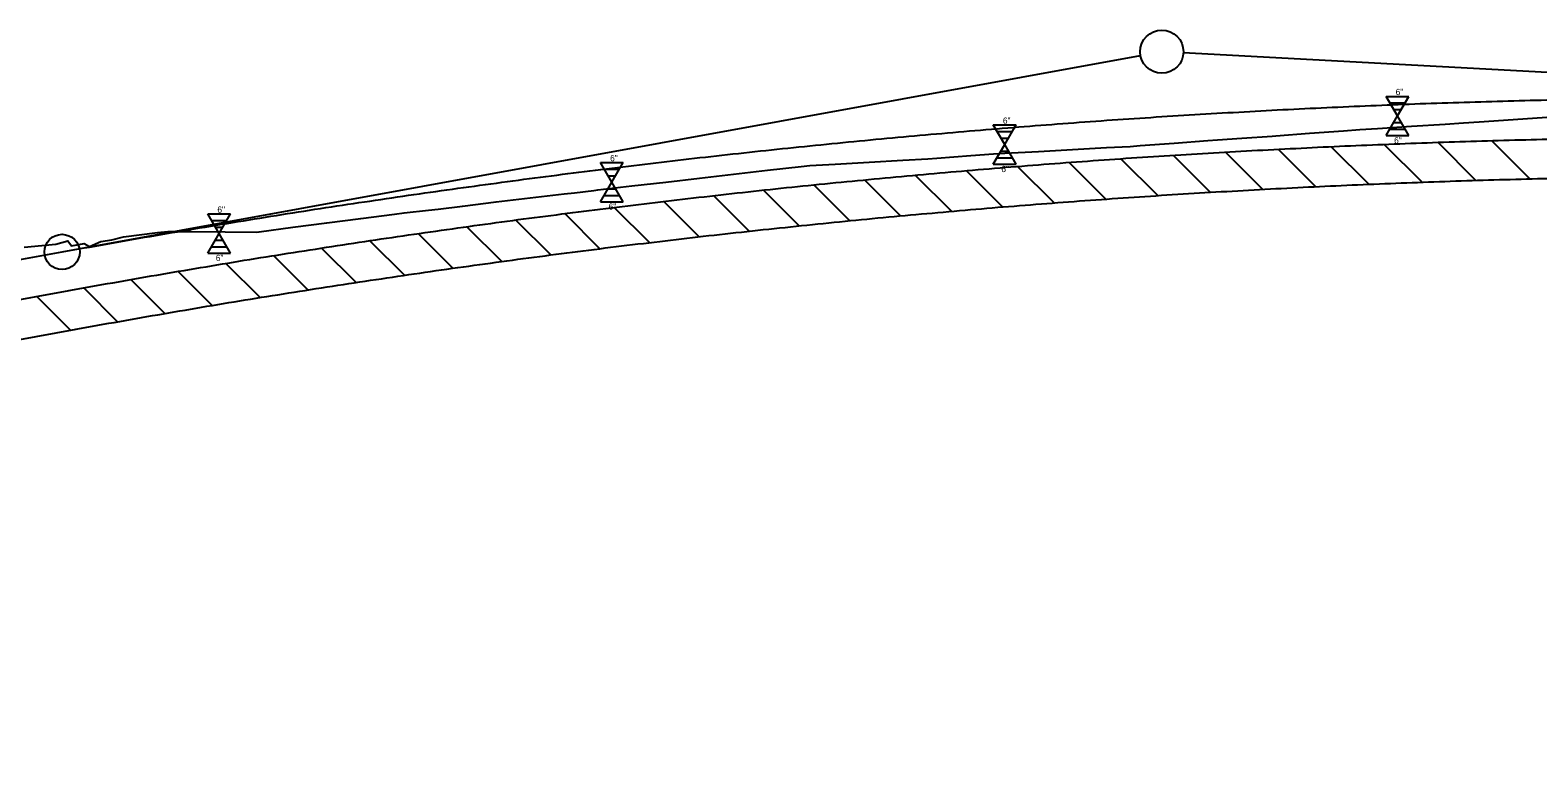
# Model space of a CAD drawing. Extents: x 579185 to 595036, y -53221 to -44640.
# Drawn here: x 584352.2 to 584544.1, y -46885.4 to -46791.5 of the extents above; entities that cross this region are included whole.
import ezdxf

# ---------------------------------------------------------------- set-up
doc = ezdxf.new("R2010")
doc.units = 0
for name, color, linetype in [('Exist Vertical Profile Ground Line', 7, 'Continuous'), ('Old_Level_2', 7, 'Continuous'), ('Prop Vertical Profile Curve Label', 7, 'Continuous'), ('Prop Vertical Profile Grade', 7, 'Continuous'), ('Prop VPI Label', 7, 'Continuous'), ('Scratch_Level_1', 7, 'Continuous')]:
    doc.layers.add(name, color=color, linetype=linetype)

msp = doc.modelspace()

# ---------------------------------------------------------------- linework, layer by layer
at = {"layer": 'Exist Vertical Profile Ground Line'}
msp.add_lwpolyline([(584351.4, -46819.17), (584355.43, -46818.8), (584356.96, -46818.38), (584357.45, -46819), (584359.06, -46818.72), (584359.75, -46819.09), (584361.16, -46818.46), (584362.57, -46818.25), (584364.06, -46817.85), (584368.38, -46817.32), (584369.71, -46817.16), (584372.69, -46817.18), (584377.01, -46817.21), (584381.02, -46817.24), (584381.32, -46817.2), (584385.64, -46816.64), (584389.95, -46816.07), (584394.26, -46815.51), (584398.58, -46814.95), (584399.79, -46814.79), (584402.89, -46814.46), (584404.13, -46814.33), (584407.21, -46813.93), (584411.52, -46813.39), (584415.84, -46812.89), (584420.15, -46812.38), (584421.47, -46812.23), (584423.92, -46811.94), (584424.46, -46811.87), (584428.78, -46811.37), (584433.09, -46810.87), (584437.41, -46810.37), (584441.72, -46809.87), (584446.04, -46809.38), (584450.35, -46808.89), (584451.42, -46808.77), (584454.66, -46808.59), (584458.98, -46808.34), (584463.29, -46808.1), (584466.46, -46807.93), (584467.61, -46807.84), (584471.92, -46807.51), (584474.8, -46807.29), (584476.24, -46807.21), (584480.55, -46806.97), (584484.86, -46806.73), (584489.18, -46806.49), (584492.21, -46806.33), (584493.49, -46806.23), (584497.81, -46805.9), (584502.12, -46805.58), (584503.32, -46805.49), (584506.44, -46805.28), (584510.27, -46805.02), (584510.75, -46804.98), (584515.06, -46804.66), (584519.38, -46804.35), (584521.46, -46804.19), (584523.69, -46804.05), (584528.01, -46803.77), (584532.32, -46803.5), (584534.65, -46803.35), (584536.64, -46803.21), (584540.95, -46802.9), (584545.26, -46802.6)], dxfattribs=at)
at = {"layer": 'Old_Level_2'}
for p, q in [((584526.24, -46802.46), (584524.79, -46799.96)), ((584524.79, -46799.96), (584527.68, -46799.96)), ((584526.24, -46802.46), (584527.68, -46799.96)), ((584524.79, -46804.96), (584526.24, -46802.46)), ((584525.27, -46800.79), (584527.2, -46800.79)), ((584525.76, -46801.63), (584526.72, -46801.63)), ((584527.68, -46804.96), (584526.24, -46802.46)), ((584476.24, -46806.1), (584474.79, -46803.6)), ((584474.79, -46803.6), (584477.68, -46803.6)), ((584475.27, -46804.44), (584477.2, -46804.44)), ((584476.24, -46806.1), (584477.68, -46803.6)), ((584525.27, -46804.13), (584527.2, -46804.13)), ((584525.75, -46803.29), (584526.72, -46803.29)), ((584474.79, -46808.6), (584476.24, -46806.1)), ((584475.76, -46805.27), (584476.72, -46805.27)), ((584477.68, -46808.61), (584476.24, -46806.1)), ((584524.79, -46804.96), (584527.68, -46804.96)), ((584475.27, -46807.77), (584477.2, -46807.77)), ((584475.75, -46806.94), (584476.72, -46806.94)), ((584426.24, -46810.9), (584424.79, -46808.4)), ((584424.79, -46808.4), (584427.68, -46808.4)), ((584425.27, -46809.23), (584427.2, -46809.23)), ((584425.76, -46810.07), (584426.72, -46810.07)), ((584426.24, -46810.9), (584427.68, -46808.4)), ((584474.79, -46808.6), (584477.68, -46808.61)), ((584424.79, -46813.4), (584426.24, -46810.9)), ((584425.75, -46811.73), (584426.72, -46811.73)), ((584427.68, -46813.4), (584426.24, -46810.9)), ((584424.79, -46813.4), (584427.68, -46813.4)), ((584425.27, -46812.57), (584427.2, -46812.57)), ((584376.24, -46817.44), (584374.79, -46814.94)), ((584374.79, -46814.94), (584377.68, -46814.94)), ((584375.27, -46815.77), (584377.2, -46815.77)), ((584376.24, -46817.44), (584377.68, -46814.94)), ((584374.79, -46819.94), (584376.24, -46817.44)), ((584375.76, -46816.61), (584376.72, -46816.61)), ((584377.68, -46819.94), (584376.24, -46817.44)), ((584375.27, -46819.11), (584377.2, -46819.11)), ((584375.75, -46818.27), (584376.72, -46818.27)), ((584374.79, -46819.94), (584377.68, -46819.94))]:
    msp.add_line(p, q, dxfattribs=at)
at = {"layer": 'Prop Vertical Profile Curve Label'}
msp.add_circle((584356.24, -46819.78), 2.25, dxfattribs=at)
at = {"layer": 'Prop Vertical Profile Grade'}
msp.add_line((583996.24, -46885.36), (584356.24, -46819.78), dxfattribs=at)
msp.add_spline([(584356.24, -46819.78), (584361.84, -46818.77), (584367.44, -46817.79), (584373.04, -46816.84), (584378.64, -46815.91), (584384.24, -46815.01), (584389.84, -46814.13), (584395.44, -46813.29), (584401.04, -46812.46), (584406.64, -46811.67), (584412.24, -46810.9), (584417.84, -46810.16), (584423.44, -46809.44), (584429.04, -46808.75), (584434.64, -46808.09), (584440.24, -46807.45), (584445.84, -46806.84), (584451.44, -46806.26), (584457.04, -46805.7), (584462.64, -46805.17), (584468.24, -46804.67), (584473.84, -46804.19), (584479.44, -46803.74), (584485.04, -46803.31), (584490.64, -46802.91), (584496.24, -46802.54), (584501.84, -46802.19), (584507.44, -46801.88), (584513.04, -46801.58), (584518.64, -46801.32), (584524.24, -46801.08), (584529.84, -46800.86), (584535.44, -46800.68), (584541.04, -46800.52), (584546.64, -46800.38), (584552.24, -46800.27), (584557.84, -46800.19), (584563.44, -46800.14), (584569.04, -46800.11), (584574.64, -46800.11), (584580.24, -46800.13), (584585.84, -46800.18), (584591.44, -46800.26), (584597.04, -46800.37), (584602.64, -46800.5), (584608.24, -46800.65), (584613.84, -46800.84), (584619.44, -46801.05), (584625.04, -46801.28), (584630.64, -46801.54), (584636.24, -46801.83)], degree=3, dxfattribs=at)
at = {"layer": 'Prop VPI Label'}
for p, q in [((584356.24, -46819.78), (584493.53, -46794.77)), ((584636.24, -46801.83), (584498.98, -46794.42))]:
    msp.add_line(p, q, dxfattribs=at)
msp.add_circle((584496.24, -46794.27), 2.75, dxfattribs=at)
at = {"layer": 'Scratch_Level_1'}
for p, q in [((584517.78, -46806.36), (584522.58, -46811.15)), ((584524.56, -46806.07), (584529.38, -46810.89)), ((584531.38, -46805.81), (584536.22, -46810.66)), ((584538.23, -46805.59), (584543.1, -46810.47)), ((584484.44, -46808.37), (584489.11, -46813.04)), ((584491.03, -46807.9), (584495.73, -46812.59)), ((584497.67, -46807.46), (584502.39, -46812.18)), ((584504.34, -46807.06), (584509.08, -46811.8)), ((584511.04, -46806.69), (584515.81, -46811.46)), ((584464.84, -46809.99), (584469.45, -46814.6)), ((584471.34, -46809.42), (584475.97, -46814.05)), ((584477.87, -46808.88), (584482.52, -46813.53)), ((584445.54, -46811.9), (584450.09, -46816.45)), ((584451.94, -46811.23), (584456.51, -46815.8)), ((584458.38, -46810.59), (584462.96, -46815.18)), ((584426.52, -46814.1), (584431.01, -46818.59)), ((584432.83, -46813.33), (584437.34, -46817.84)), ((584439.17, -46812.6), (584443.7, -46817.13)), ((584413.99, -46815.71), (584418.45, -46820.16)), ((584420.24, -46814.89), (584424.72, -46819.36)), ((584401.58, -46817.44), (584406, -46821.86)), ((584407.77, -46816.56), (584412.21, -46820.99)), ((584389.28, -46819.28), (584393.67, -46823.66)), ((584395.42, -46818.34), (584399.82, -46822.75)), ((584377.09, -46821.23), (584381.44, -46825.58)), ((584383.17, -46820.24), (584387.54, -46824.61)), ((584365, -46823.29), (584369.33, -46827.61)), ((584371.03, -46822.25), (584375.37, -46826.59)), ((584176.24, -46857.65), (584357.13, -46824.7)), ((584353.02, -46825.45), (584357.32, -46829.75)), ((584359.01, -46824.36), (584363.31, -46828.67)), ((584176.24, -46862.74), (584358.03, -46829.62))]:
    msp.add_line(p, q, dxfattribs=at)
for points in [[(584357.12, -46824.7), (584362.71, -46823.69), (584368.29, -46822.72), (584373.87, -46821.77), (584379.44, -46820.84), (584385.02, -46819.95), (584390.6, -46819.08), (584396.17, -46818.23), (584401.75, -46817.41), (584407.33, -46816.62), (584412.91, -46815.85), (584418.48, -46815.12), (584424.06, -46814.4), (584429.64, -46813.72), (584435.21, -46813.06), (584440.79, -46812.42), (584446.37, -46811.81), (584451.94, -46811.23), (584457.52, -46810.68), (584463.1, -46810.15), (584468.67, -46809.65), (584474.25, -46809.17), (584479.83, -46808.72), (584485.4, -46808.3), (584490.98, -46807.9), (584496.56, -46807.53), (584502.13, -46807.19), (584507.71, -46806.87), (584513.29, -46806.58), (584518.86, -46806.31), (584524.44, -46806.07), (584530.02, -46805.86), (584535.59, -46805.67), (584541.17, -46805.51), (584546.74, -46805.38), (584552.32, -46805.27), (584557.9, -46805.19), (584563.47, -46805.14), (584569.05, -46805.11), (584574.63, -46805.11), (584580.2, -46805.13), (584585.78, -46805.18), (584591.36, -46805.26), (584596.93, -46805.36), (584602.51, -46805.49), (584608.08, -46805.65), (584613.66, -46805.83), (584619.24, -46806.04), (584624.81, -46806.28), (584630.39, -46806.54), (584635.98, -46806.83)], [(584358.01, -46829.62), (584363.58, -46828.62), (584369.14, -46827.65), (584374.69, -46826.7), (584380.25, -46825.78), (584385.8, -46824.89), (584391.36, -46824.02), (584396.91, -46823.18), (584402.47, -46822.36), (584408.02, -46821.57), (584413.57, -46820.81), (584419.13, -46820.07), (584424.68, -46819.36), (584430.24, -46818.68), (584435.79, -46818.02), (584441.34, -46817.39), (584446.9, -46816.79), (584452.45, -46816.21), (584458, -46815.65), (584463.56, -46815.13), (584469.11, -46814.63), (584474.66, -46814.15), (584480.22, -46813.71), (584485.77, -46813.28), (584491.32, -46812.89), (584496.88, -46812.52), (584502.43, -46812.18), (584507.98, -46811.86), (584513.54, -46811.57), (584519.09, -46811.31), (584524.64, -46811.07), (584530.19, -46810.86), (584535.75, -46810.67), (584541.3, -46810.51), (584546.85, -46810.38), (584552.41, -46810.27), (584557.96, -46810.19), (584563.51, -46810.14), (584569.06, -46810.11), (584574.62, -46810.11), (584580.17, -46810.13), (584585.72, -46810.18), (584591.27, -46810.26), (584596.83, -46810.36), (584602.38, -46810.49), (584607.93, -46810.65), (584613.49, -46810.83), (584619.04, -46811.04), (584624.59, -46811.27), (584630.14, -46811.53), (584635.72, -46811.82)]]:
    msp.add_spline(points, degree=3, dxfattribs=at)

# ---------------------------------------------------------------- texts
at = {"layer": 'Old_Level_2'}
for p in [(584526.01, -46799.8), (584476.01, -46803.45), (584525.81, -46805.96), (584426.01, -46808.24), (584475.81, -46809.61), (584376.01, -46814.78), (584425.81, -46814.4), (584375.81, -46820.94)]:
    msp.add_text('6"', height=0.8, dxfattribs=at).set_placement(p)

doc.saveas('drawing.dxf')
